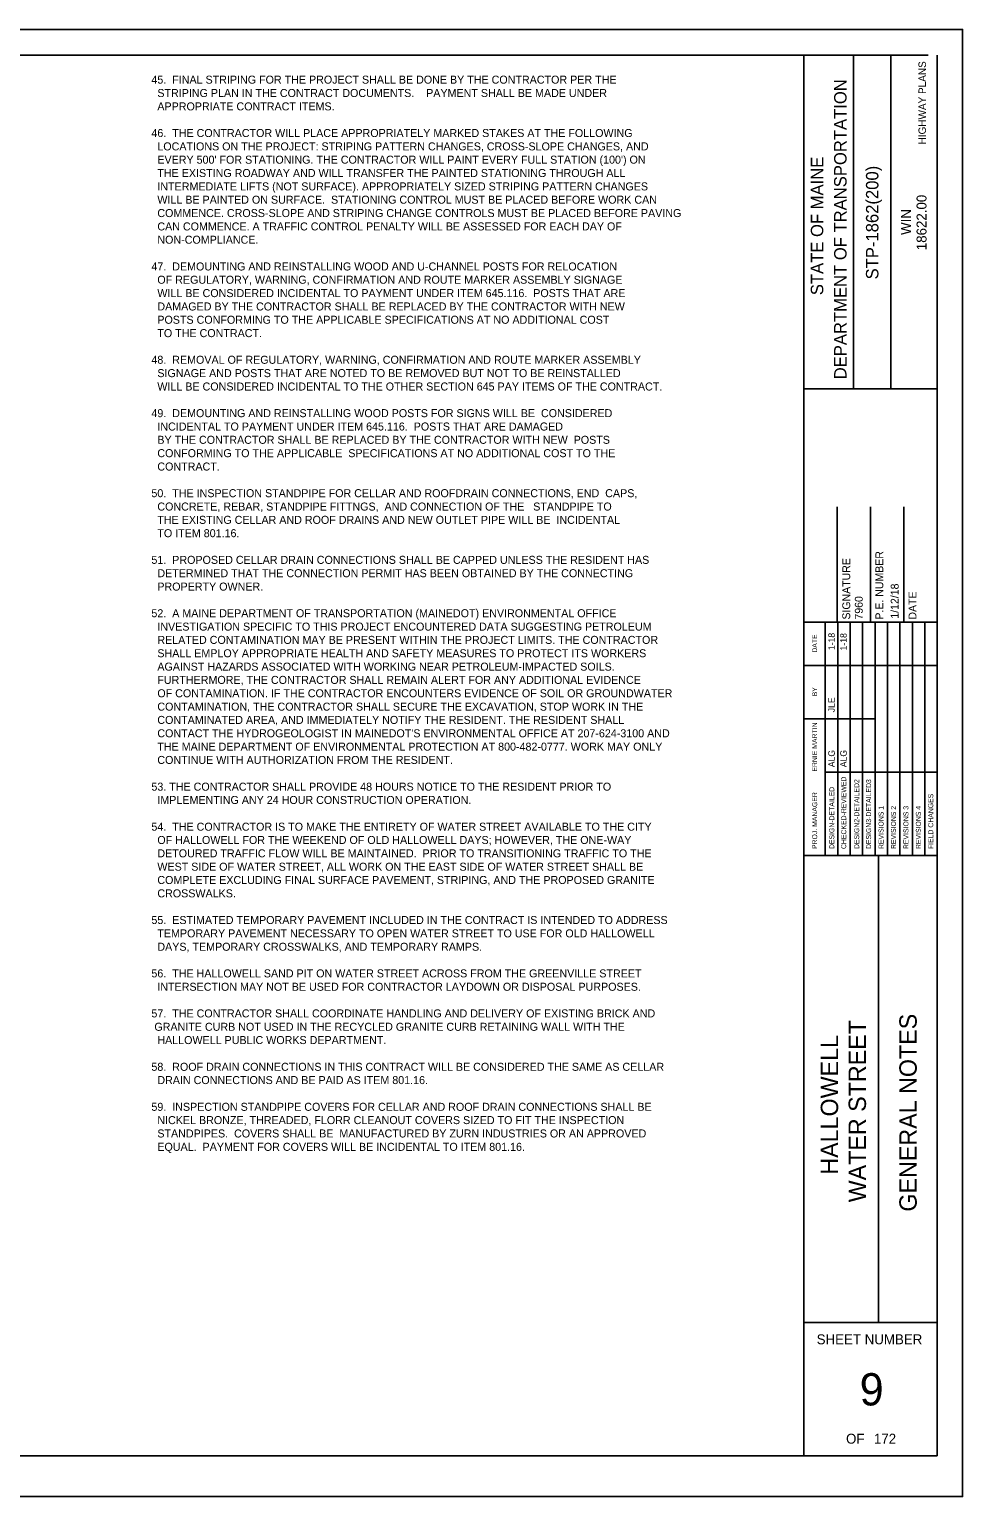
# Model space of a CAD drawing. Extents: x -0.13 to 2.7, y -0.05 to 1.78.
# Drawn here: x 1.533 to 2.698, y -0.051 to 1.782 of the extents above; entities that cross this region are included whole.
import ezdxf

# ---------------------------------------------------------------- set-up
doc = ezdxf.new("R2010")
doc.units = 0
for name, color, linetype in [('ANNOTATION', 7, 'Continuous'), ('BORDER', 7, 'Continuous'), ('PLOT BOUNDARY', 7, 'Continuous')]:
    doc.layers.add(name, color=color, linetype=linetype)

msp = doc.modelspace()

# ---------------------------------------------------------------- linework, layer by layer
at = {"layer": 'BORDER'}
for p, q in [((2.6553, 1.75), (0, 1.75)), ((2.5, 0), (2.5, 1.75)), ((2.5621, 1.3333), (2.5621, 1.75)), ((2.6087, 1.3333), (2.6087, 1.75)), ((2.6667, 0), (2.6667, 1.75)), ((2.5, 1.3332), (2.6667, 1.3332)), ((2.5417, 1.0417), (2.5417, 1.1858)), ((2.5833, 1.0417), (2.5833, 1.1858)), ((2.625, 1.0417), (2.625, 1.1858)), ((2.5, 1.0417), (2.6667, 1.0417)), ((2.5, 0.75), (2.6667, 0.75)), ((2.5932, 0.1667), (2.5932, 0.75)), ((2.5, 0.1667), (2.6667, 0.1667)), ((0, 0), (2.6667, 0))]:
    msp.add_line(p, q, dxfattribs=at)
for points in [[(2.5269, 0.9875), (2.5269, 1.0417)], [(2.5269, 0.7501), (2.5269, 1.0299)], [(2.5425, 0.7501), (2.5425, 1.0417)], [(2.558, 1.0417), (2.558, 0.7501)], [(2.5735, 0.7501), (2.5735, 1.0417)], [(2.589, 0.7501), (2.589, 1.0417)], [(2.6046, 0.7501), (2.6046, 1.0417)], [(2.6201, 0.7501), (2.6201, 1.0417)], [(2.6356, 0.7501), (2.6356, 1.0417)], [(2.6512, 0.7501), (2.6512, 1.0417)], [(2.5, 0.9875), (2.6667, 0.9875)], [(2.5, 0.9209), (2.5269, 0.9209)], [(2.5269, 0.9209), (2.589, 0.9209)], [(2.5269, 0.8542), (2.6667, 0.8542)]]:
    msp.add_lwpolyline(points, dxfattribs=at)
at = {"layer": 'PLOT BOUNDARY'}
msp.add_lwpolyline([(-0.1349, -0.051), (2.6984, -0.051), (2.6984, 1.7823), (-0.1349, 1.7823)], close=True, dxfattribs=at)

# ---------------------------------------------------------------- texts
at = {"layer": 'ANNOTATION'}
for s, p in [('45.  FINAL STRIPING FOR THE PROJECT SHALL BE DONE BY THE CONTRACTOR PER THE ', (1.685, 1.7145)), ('  STRIPING PLAN IN THE CONTRACT DOCUMENTS.    PAYMENT SHALL BE MADE UNDER ', (1.685, 1.6978)), ('  APPROPRIATE CONTRACT ITEMS.', (1.685, 1.6811)), ('46.  THE CONTRACTOR WILL PLACE APPROPRIATELY MARKED STAKES AT THE FOLLOWING ', (1.685, 1.6478)), ('  LOCATIONS ON THE PROJECT: STRIPING PATTERN CHANGES, CROSS-SLOPE CHANGES, AND ', (1.685, 1.6311)), ("  EVERY 500' FOR STATIONING. THE CONTRACTOR WILL PAINT EVERY FULL STATION (100') ON ", (1.685, 1.6145)), ('  THE EXISTING ROADWAY AND WILL TRANSFER THE PAINTED STATIONING THROUGH ALL ', (1.685, 1.5978)), ('  INTERMEDIATE LIFTS (NOT SURFACE). APPROPRIATELY SIZED STRIPING PATTERN CHANGES ', (1.685, 1.5811)), ('  WILL BE PAINTED ON SURFACE.  STATIONING CONTROL MUST BE PLACED BEFORE WORK CAN ', (1.685, 1.5645)), ('  COMMENCE. CROSS-SLOPE AND STRIPING CHANGE CONTROLS MUST BE PLACED BEFORE PAVING ', (1.685, 1.5478)), ('  CAN COMMENCE. A TRAFFIC CONTROL PENALTY WILL BE ASSESSED FOR EACH DAY OF ', (1.685, 1.5311)), ('  NON-COMPLIANCE.', (1.685, 1.5145)), ('47.  DEMOUNTING AND REINSTALLING WOOD AND U-CHANNEL POSTS FOR RELOCATION ', (1.685, 1.4811)), ('  OF REGULATORY, WARNING, CONFIRMATION AND ROUTE MARKER ASSEMBLY SIGNAGE ', (1.685, 1.4645)), ('  WILL BE CONSIDERED INCIDENTAL TO PAYMENT UNDER ITEM 645.116.  POSTS THAT ARE ', (1.685, 1.4478)), ('  DAMAGED BY THE CONTRACTOR SHALL BE REPLACED BY THE CONTRACTOR WITH NEW ', (1.685, 1.4311)), ('  POSTS CONFORMING TO THE APPLICABLE SPECIFICATIONS AT NO ADDITIONAL COST ', (1.685, 1.4145)), ('  TO THE CONTRACT.', (1.685, 1.3978)), ('48.  REMOVAL OF REGULATORY, WARNING, CONFIRMATION AND ROUTE MARKER ASSEMBLY ', (1.685, 1.3645)), ('  SIGNAGE AND POSTS THAT ARE NOTED TO BE REMOVED BUT NOT TO BE REINSTALLED ', (1.685, 1.3478)), ('  WILL BE CONSIDERED INCIDENTAL TO THE OTHER SECTION 645 PAY ITEMS OF THE CONTRACT.  ', (1.685, 1.3311)), ('49.  DEMOUNTING AND REINSTALLING WOOD POSTS FOR SIGNS WILL BE  CONSIDERED ', (1.685, 1.2978)), ('  INCIDENTAL TO PAYMENT UNDER ITEM 645.116.  POSTS THAT ARE DAMAGED ', (1.685, 1.2811)), ('  BY THE CONTRACTOR SHALL BE REPLACED BY THE CONTRACTOR WITH NEW  POSTS ', (1.685, 1.2645)), ('  CONFORMING TO THE APPLICABLE  SPECIFICATIONS AT NO ADDITIONAL COST TO THE ', (1.685, 1.2478)), ('  CONTRACT.', (1.685, 1.2311)), ('50.  THE INSPECTION STANDPIPE FOR CELLAR AND ROOFDRAIN CONNECTIONS, END  CAPS,  ', (1.685, 1.1978)), ('  THE EXISTING CELLAR AND ROOF DRAINS AND NEW OUTLET PIPE WILL BE  INCIDENTAL ', (1.685, 1.1645)), ('  CONCRETE, REBAR, STANDPIPE FITTNGS,  AND CONNECTION OF THE   STANDPIPE TO ', (1.685, 1.1811)), ('  TO ITEM 801.16.', (1.685, 1.1478)), ('51.  PROPOSED CELLAR DRAIN CONNECTIONS SHALL BE CAPPED UNLESS THE RESIDENT HAS ', (1.685, 1.1145)), ('  DETERMINED THAT THE CONNECTION PERMIT HAS BEEN OBTAINED BY THE CONNECTING ', (1.685, 1.0978)), ('  PROPERTY OWNER.', (1.685, 1.0811)), ('52.  A MAINE DEPARTMENT OF TRANSPORTATION (MAINEDOT) ENVIRONMENTAL OFFICE ', (1.685, 1.0478)), ('  INVESTIGATION SPECIFIC TO THIS PROJECT ENCOUNTERED DATA SUGGESTING PETROLEUM ', (1.685, 1.0311)), ('  RELATED CONTAMINATION MAY BE PRESENT WITHIN THE PROJECT LIMITS. THE CONTRACTOR', (1.685, 1.0145)), ('  AGAINST HAZARDS ASSOCIATED WITH WORKING NEAR PETROLEUM-IMPACTED SOILS. ', (1.685, 0.9811)), ('  SHALL EMPLOY APPROPRIATE HEALTH AND SAFETY MEASURES TO PROTECT ITS WORKERS ', (1.685, 0.9978)), ('  FURTHERMORE, THE CONTRACTOR SHALL REMAIN ALERT FOR ANY ADDITIONAL EVIDENCE', (1.685, 0.9645)), ('  OF CONTAMINATION. IF THE CONTRACTOR ENCOUNTERS EVIDENCE OF SOIL OR GROUNDWATER ', (1.685, 0.9478)), ('  CONTAMINATION, THE CONTRACTOR SHALL SECURE THE EXCAVATION, STOP WORK IN THE ', (1.685, 0.9311)), ('  CONTAMINATED AREA, AND IMMEDIATELY NOTIFY THE RESIDENT. THE RESIDENT SHALL ', (1.685, 0.9145)), ("  CONTACT THE HYDROGEOLOGIST IN MAINEDOT'S ENVIRONMENTAL OFFICE AT 207-624-3100 AND ", (1.685, 0.8978)), ('  THE MAINE DEPARTMENT OF ENVIRONMENTAL PROTECTION AT 800-482-0777. WORK MAY ONLY ', (1.685, 0.8811)), ('  CONTINUE WITH AUTHORIZATION FROM THE RESIDENT.', (1.685, 0.8645)), ('53. THE CONTRACTOR SHALL PROVIDE 48 HOURS NOTICE TO THE RESIDENT PRIOR TO', (1.685, 0.8311)), ('  IMPLEMENTING ANY 24 HOUR CONSTRUCTION OPERATION.', (1.685, 0.8145)), ('54.  THE CONTRACTOR IS TO MAKE THE ENTIRETY OF WATER STREET AVAILABLE TO THE CITY', (1.685, 0.7811)), ('  OF HALLOWELL FOR THE WEEKEND OF OLD HALLOWELL DAYS; HOWEVER, THE ONE-WAY', (1.685, 0.7645)), ('  DETOURED TRAFFIC FLOW WILL BE MAINTAINED.  PRIOR TO TRANSITIONING TRAFFIC TO THE ', (1.685, 0.7478)), ('  WEST SIDE OF WATER STREET, ALL WORK ON THE EAST SIDE OF WATER STREET SHALL BE ', (1.685, 0.7311)), ('  COMPLETE EXCLUDING FINAL SURFACE PAVEMENT, STRIPING, AND THE PROPOSED GRANITE', (1.685, 0.7145)), ('  CROSSWALKS.', (1.685, 0.6978)), ('55.  ESTIMATED TEMPORARY PAVEMENT INCLUDED IN THE CONTRACT IS INTENDED TO ADDRESS', (1.685, 0.6645)), ('  TEMPORARY PAVEMENT NECESSARY TO OPEN WATER STREET TO USE FOR OLD HALLOWELL ', (1.685, 0.6478)), ('  DAYS, TEMPORARY CROSSWALKS, AND TEMPORARY RAMPS.', (1.685, 0.6311)), ('56.  THE HALLOWELL SAND PIT ON WATER STREET ACROSS FROM THE GREENVILLE STREET ', (1.685, 0.5978)), ('  INTERSECTION MAY NOT BE USED FOR CONTRACTOR LAYDOWN OR DISPOSAL PURPOSES.', (1.685, 0.5811)), ('57.  THE CONTRACTOR SHALL COORDINATE HANDLING AND DELIVERY OF EXISTING BRICK AND ', (1.685, 0.5478)), (' GRANITE CURB NOT USED IN THE RECYCLED GRANITE CURB RETAINING WALL WITH THE ', (1.685, 0.5311)), ('  HALLOWELL PUBLIC WORKS DEPARTMENT.', (1.685, 0.5145)), ('58.  ROOF DRAIN CONNECTIONS IN THIS CONTRACT WILL BE CONSIDERED THE SAME AS CELLAR', (1.685, 0.4811)), ('  DRAIN CONNECTIONS AND BE PAID AS ITEM 801.16.', (1.685, 0.4645)), ('59.  INSPECTION STANDPIPE COVERS FOR CELLAR AND ROOF DRAIN CONNECTIONS SHALL BE', (1.685, 0.4311)), ('  NICKEL BRONZE, THREADED, FLORR CLEANOUT COVERS SIZED TO FIT THE INSPECTION ', (1.685, 0.4145)), ('  STANDPIPES.  COVERS SHALL BE  MANUFACTURED BY ZURN INDUSTRIES OR AN APPROVED', (1.685, 0.3978)), ('  EQUAL.  PAYMENT FOR COVERS WILL BE INCIDENTAL TO ITEM 801.16.', (1.685, 0.3811))]:
    msp.add_text(s, height=0.01, dxfattribs=at).set_placement(p)
at = {"layer": 'BORDER'}
for s, height, p in [('HIGHWAY PLANS', 0.009317, (2.6526, 1.6386)), ('DEPARTMENT OF TRANSPORTATION', 0.015529, (2.5534, 1.3451)), ('STATE OF MAINE', 0.015529, (2.5243, 1.4502)), ('STP-1862(200)', 0.015529, (2.5932, 1.4699)), ('18622.00', 0.01242, (2.6533, 1.5064)), ('WIN', 0.01242, (2.6339, 1.5255)), ('SIGNATURE', 0.00984, (2.558, 1.0449)), ('P.E. NUMBER', 0.009843, (2.5993, 1.0449)), ('1/12/18', 0.00984, (2.6185, 1.046)), ('7960', 0.00984, (2.5736, 1.0449)), ('DATE', 0.00984, (2.6407, 1.0449)), ('1-18', 0.00808, (2.5387, 1.0067)), ('1-18', 0.00808, (2.5536, 1.0063)), ('DATE', 0.00619, (2.5167, 1.0035)), ('BY', 0.00619, (2.5167, 0.949)), ('JLE', 0.00808, (2.5387, 0.929)), ('ERNIE MARTIN', 0.006212, (2.5167, 0.8549)), ('ALG', 0.00808, (2.5387, 0.8604)), ('ALG', 0.00808, (2.5536, 0.8604)), ('CHECKED-REVIEWED', 0.006212, (2.553, 0.7582)), ('PROJ. MANAGER', 0.006212, (2.5167, 0.7582)), ('DESIGN-DETAILED', 0.006212, (2.5381, 0.7582)), ('DESIGN2-DETAILED2', 0.006212, (2.5692, 0.7582)), ('DESIGN3-DETAILED3', 0.006212, (2.5841, 0.7582)), ('REVISIONS 1', 0.006212, (2.5996, 0.7582)), ('REVISIONS 2', 0.006212, (2.6151, 0.7582)), ('REVISIONS 3', 0.006212, (2.6307, 0.7582)), ('REVISIONS 4', 0.006212, (2.6462, 0.7582)), ('FIELD CHANGES', 0.006212, (2.6617, 0.7582)), ('GENERAL NOTES', 0.021738, (2.6411, 0.3052)), ('WATER STREET', 0.021738, (2.5777, 0.3168)), ('HALLOWELL', 0.02174, (2.5429, 0.3513))]:
    msp.add_text(s, height=height, rotation=90, dxfattribs=at).set_placement(p)
for s, height, p in [('SHEET NUMBER', 0.012421, (2.5161, 0.1394)), ('9', 0.0403, (2.5698, 0.063)), ('OF', 0.01242, (2.5528, 0.0152)), ('172', 0.01242, (2.5876, 0.0152))]:
    msp.add_text(s, height=height, dxfattribs=at).set_placement(p)

doc.saveas('drawing.dxf')
